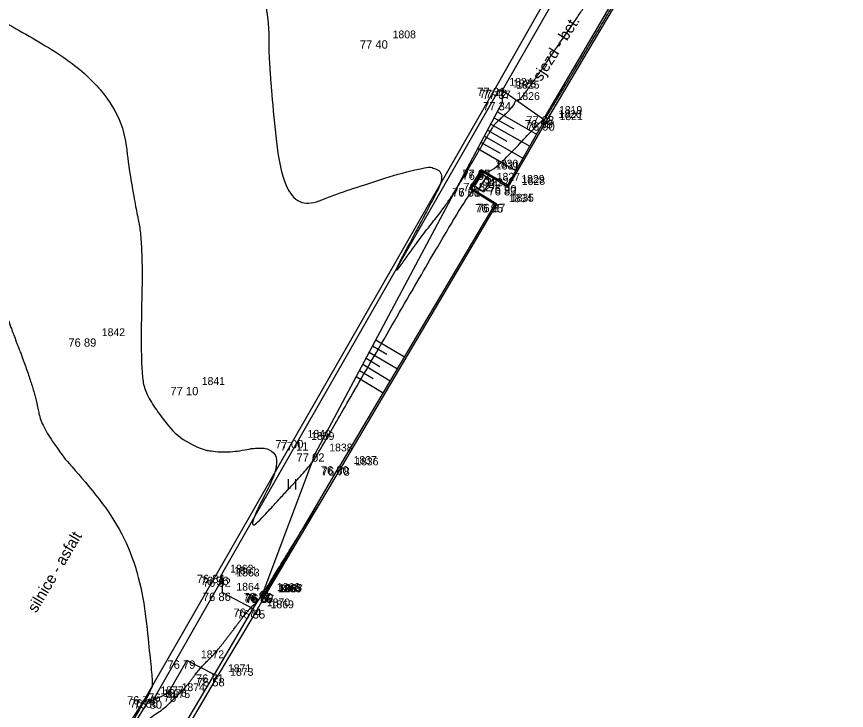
# Model space of a CAD drawing. Extents: x -704017 to -701500, y -1008977 to -1008450.
# Drawn here: x -701574.39 to -701544.66, y -1008544.23 to -1008519.37 of the extents above; entities that cross this region are included whole.
import ezdxf

# ---------------------------------------------------------------- set-up
doc = ezdxf.new("R2010")
doc.units = 0
for name, color, linetype in [('Z_body', 7, 'Continuous'), ('Z_body_cisla', 7, 'Continuous'), ('Z_body_vysky', 7, 'Continuous'), ('Z_chodnik', 7, 'Continuous'), ('Z_komunikace', 7, 'Continuous'), ('Z_obruby', 7, 'Continuous'), ('Z_popis', 7, 'Continuous'), ('Z_rozhrani_ploch', 7, 'Continuous'), ('Z_site_znaky_kanalizace', 7, 'Continuous'), ('Z_site_znaky_vodovod', 7, 'Continuous'), ('Z_teren_hrany_paty', 7, 'Continuous'), ('Z_vrstevnice_hlavni', 7, 'Continuous'), ('Z_vrstevnice_vedlejsi', 7, 'Continuous')]:
    doc.layers.add(name, color=color, linetype=linetype)

# ---------------------------------------------------------------- blocks, each defined once
blk = doc.blocks.new('POINT_DISPLAY')
blk.add_line((0, 0), (0, 0))
blk = doc.blocks.new('Z306')
for p, q in [((-0.13, 0.17), (-0.13, -0.2)), ((0.13, 0.17), (0.13, -0.2))]:
    blk.add_line(p, q)
blk = doc.blocks.new('Z38')
for p, q in [((0.25, 0.2), (-0.25, 0.2)), ((-0.25, 0.2), (-0.25, -0.2)), ((-0.25, 0), (0.25, 0)), ((0.25, -0.2), (0.25, 0.2)), ((-0.25, -0.2), (0.25, -0.2))]:
    blk.add_line(p, q)
blk = doc.blocks.new('Z614')
for p, q in [((-0.13, 0.03), (-0.1, 0.08)), ((-0.13, -0.03), (-0.13, 0.03)), ((-0.1, 0.08), (-0.08, 0.1)), ((-0.08, 0.1), (-0.03, 0.13)), ((-0.03, 0.13), (0.03, 0.13)), ((0.03, 0.13), (0.08, 0.1)), ((0.08, 0.1), (0.1, 0.08)), ((0.1, 0.08), (0.13, 0.03)), ((0.13, 0.03), (0.13, -0.03)), ((-0.1, -0.08), (-0.13, -0.03)), ((-0.08, -0.1), (-0.1, -0.08)), ((-0.03, -0.13), (-0.08, -0.1)), ((0.03, -0.13), (-0.03, -0.13)), ((0.08, -0.1), (0.03, -0.13)), ((0.1, -0.08), (0.08, -0.1)), ((0.13, -0.03), (0.1, -0.08))]:
    blk.add_line(p, q)

msp = doc.modelspace()

# ---------------------------------------------------------------- linework, layer by layer
at = {"layer": 'Z_chodnik'}
for p, q in [((-701552.79, -1008518.67), (-701555.44, -1008523.16)), ((-701555.44, -1008523.16), (-701556.79, -1008525.48)), ((-701557.72, -1008524.92), (-701558.09, -1008525.52)), ((-701556.79, -1008525.48), (-701557.72, -1008524.92)), ((-701558.09, -1008525.52), (-701557.19, -1008526.08)), ((-701557.19, -1008526.08), (-701562.76, -1008535.52)), ((-701562.76, -1008535.52), (-701565.47, -1008540.08)), ((-701565.47, -1008540.08), (-701565.79, -1008540.64)), ((-701565.79, -1008540.64), (-701567.24, -1008543.07)), ((-701567.24, -1008543.07), (-701568.22, -1008544.75))]:
    msp.add_line(p, q, dxfattribs=at)
at = {"layer": 'Z_komunikace'}
for p, q in [((-701554.72, -1008517.51), (-701557.24, -1008521.92)), ((-701557.24, -1008521.92), (-701564.47, -1008534.54)), ((-701564.47, -1008534.54), (-701567.24, -1008539.37)), ((-701569.74, -1008543.72), (-701567.24, -1008539.37)), ((-701569.74, -1008543.72), (-701571.74, -1008546.87))]:
    msp.add_line(p, q, dxfattribs=at)
at = {"layer": 'Z_obruby'}
for p, q in [((-701554.5, -1008517.65), (-701556.99, -1008522.02)), ((-701553.11, -1008518.96), (-701555.46, -1008522.94)), ((-701557.11, -1008521.99), (-701564.34, -1008534.62)), ((-701556.99, -1008522.02), (-701557.11, -1008521.99)), ((-701555.48, -1008523.08), (-701556.81, -1008525.41)), ((-701555.46, -1008522.94), (-701555.48, -1008523.08)), ((-701557.75, -1008524.86), (-701558.16, -1008525.52)), ((-701556.81, -1008525.41), (-701557.75, -1008524.86)), ((-701558.16, -1008525.52), (-701557.26, -1008526.09)), ((-701557.26, -1008526.09), (-701562.82, -1008535.48)), ((-701564.34, -1008534.62), (-701567.1, -1008539.44)), ((-701565.5, -1008540.05), (-701562.82, -1008535.48)), ((-701567.1, -1008539.44), (-701567.02, -1008539.5)), ((-701567.02, -1008539.5), (-701569.51, -1008543.87)), ((-701565.57, -1008540.02), (-701565.93, -1008540.58)), ((-701565.5, -1008540.05), (-701565.57, -1008540.02)), ((-701565.93, -1008540.58), (-701567.32, -1008542.94)), ((-701567.32, -1008542.94), (-701568.33, -1008544.65)), ((-701569.63, -1008543.83), (-701571.63, -1008546.96)), ((-701569.51, -1008543.87), (-701569.63, -1008543.83))]:
    msp.add_line(p, q, dxfattribs=at)
at = {"layer": 'Z_rozhrani_ploch'}
for p, q in [((-701555.48, -1008523.08), (-701556.99, -1008522.02)), ((-701555.46, -1008522.94), (-701555.48, -1008523.08)), ((-701567.02, -1008540.01), (-701567.02, -1008539.5)), ((-701567.02, -1008540.01), (-701565.93, -1008540.58)), ((-701568.29, -1008542.44), (-701568.98, -1008543.62)), ((-701567.32, -1008542.94), (-701568.29, -1008542.44)), ((-701568.98, -1008543.62), (-701569.51, -1008543.87))]:
    msp.add_line(p, q, dxfattribs=at)
at = {"layer": 'Z_teren_hrany_paty'}
for p, q in [((-701556.98, -1008522.43), (-701556.99, -1008522.02)), ((-701556.98, -1008522.43), (-701563.69, -1008535.02)), ((-701557.16, -1008522.78), (-701555.76, -1008523.58)), ((-701557.28, -1008523), (-701556.58, -1008523.39)), ((-701557.4, -1008523.22), (-701556.01, -1008524.01)), ((-701557.63, -1008523.66), (-701556.26, -1008524.44)), ((-701557.52, -1008523.44), (-701556.83, -1008523.83)), ((-701557.75, -1008523.88), (-701557.07, -1008524.27)), ((-701557.87, -1008524.1), (-701556.51, -1008524.88)), ((-701561.52, -1008530.95), (-701560.5, -1008531.56)), ((-701561.76, -1008531.39), (-701560.75, -1008531.99)), ((-701561.64, -1008531.17), (-701561.13, -1008531.47)), ((-701561.87, -1008531.61), (-701561.38, -1008531.91)), ((-701561.99, -1008531.83), (-701561.01, -1008532.42)), ((-701562.23, -1008532.27), (-701561.26, -1008532.85)), ((-701562.11, -1008532.05), (-701561.62, -1008532.34)), ((-701563.69, -1008535.02), (-701565.57, -1008540.02))]:
    msp.add_line(p, q, dxfattribs=at)
at = {"layer": 'Z_vrstevnice_hlavni'}
msp.add_open_spline([(-701579.898, -1008517.403), (-701579.435, -1008517.461), (-701579.227, -1008517.484), (-701578.62, -1008517.429), (-701578.136, -1008517.429), (-701578.069, -1008517.412), (-701577.945, -1008517.378), (-701577.257, -1008518.262), (-701570.798, -1008521.775), (-701570.216, -1008525.84), (-701569.854, -1008527.425), (-701569.965, -1008531.811), (-701569.749, -1008533.131), (-701567.868, -1008535.228), (-701564.47, -1008534.54), (-701566.364, -1008538.155), (-701564.827, -1008536.493), (-701563.84, -1008535.42), (-701563.611, -1008535.062), (-701558.382, -1008525.994), (-701558.01, -1008525.615), (-701558.155, -1008525.52), (-701557.85, -1008525.054), (-701557.738, -1008524.883), (-701557.437, -1008525.043), (-701555.858, -1008523.377), (-701555.523, -1008523.061), (-701555.52, -1008523.052), (-701555.478, -1008523.064), (-701555.451, -1008523.038), (-701554.427, -1008521.334), (-701552.912, -1008518.78), (-701552.83, -1008518.643), (-701552.822, -1008518.618), (-701552.869, -1008518.575), (-701552.419, -1008517.944), (-701552.058, -1008517.342), (-701550.92, -1008515.45), (-701550.945, -1008516.008)], degree=2, dxfattribs=at)
at = {"layer": 'Z_vrstevnice_vedlejsi'}
for points in [[(-701575.752, -1008514.26), (-701574.817, -1008512.777), (-701573.926, -1008511.316), (-701570.695, -1008512.711), (-701569.42, -1008512.917), (-701566.67, -1008515.095), (-701566.175, -1008515.153), (-701565.67, -1008518.087), (-701565.342, -1008519.528), (-701565.377, -1008520.923), (-701564.84, -1008526.43), (-701562.564, -1008525.59), (-701558.639, -1008524.363), (-701560.089, -1008527.07), (-701561.075, -1008528.916), (-701559.86, -1008527.2), (-701558.867, -1008525.971), (-701557.302, -1008523.273), (-701557.219, -1008523.184), (-701556.594, -1008522.597), (-701556.513, -1008522.355), (-701556.357, -1008522.401), (-701554.888, -1008520.254), (-701553.753, -1008518.595), (-701553.721, -1008518.39), (-701553.438, -1008518.164), (-701553.603, -1008518.013), (-701550.512, -1008513.673), (-701549.42, -1008512.077), (-701548.525, -1008510.814), (-701546.565, -1008507.745), (-701545.255, -1008505.496), (-701544.661, -1008504.504)], [(-701581.484, -1008520.098), (-701581.044, -1008520.351), (-701576.589, -1008526.756), (-701576.279, -1008527.273), (-701576.148, -1008527.441), (-701575.257, -1008527.926), (-701575.052, -1008529.352), (-701573.738, -1008532.728), (-701573.472, -1008534.358), (-701570.098, -1008538.119), (-701569.49, -1008543.285), (-701569.589, -1008543.486), (-701569.702, -1008543.745), (-701569.731, -1008543.729), (-701570.49, -1008545.069), (-701570.924, -1008545.855), (-701569.908, -1008544.918), (-701569.741, -1008544.578), (-701569.089, -1008544.149), (-701568.817, -1008543.878), (-701568.269, -1008543.329), (-701567.805, -1008542.69), (-701567.24, -1008542.159), (-701566.021, -1008540.533), (-701565.81, -1008540.393), (-701565.563, -1008540.03), (-701565.552, -1008540.028), (-701564.038, -1008537.557), (-701563.673, -1008537.03), (-701563.499, -1008536.764)], [(-701583.758, -1008524.378), (-701583.725, -1008524.396), (-701583.247, -1008525.084), (-701581.8, -1008527.754), (-701577.643, -1008535.405), (-701577.276, -1008535.989), (-701577.056, -1008537.148), (-701576.362, -1008543.879), (-701576.184, -1008545.1), (-701576.039, -1008545.424), (-701575.362, -1008546.368), (-701572.955, -1008548.603), (-701573.208, -1008549.082), (-701573.733, -1008549.961), (-701572.633, -1008549.614), (-701571.446, -1008548.497), (-701569.669, -1008545.652), (-701568.82, -1008545.14), (-701568.628, -1008545.02), (-701569.284, -1008546.389), (-701568.639, -1008545.441), (-701568.592, -1008545.371), (-701568.307, -1008545.091)], [(-701586.638, -1008530.149), (-701583.606, -1008535.727), (-701581.404, -1008539.231), (-701581.171, -1008540.459), (-701580.149, -1008543.901), (-701579.652, -1008547.301), (-701578.785, -1008549.245), (-701576.755, -1008552.075), (-701575.994, -1008552.799), (-701577.127, -1008554.481), (-701577.189, -1008554.565), (-701577.075, -1008554.54), (-701577.032, -1008554.582), (-701576.659, -1008554.828), (-701574.932, -1008553.415), (-701573.952, -1008553.106), (-701573.41, -1008552.597), (-701571.145, -1008548.968), (-701572.423, -1008551.634), (-701572.129, -1008551.201), (-701571.692, -1008550.549), (-701571.051, -1008549.918)]]:
    msp.add_open_spline(points, degree=2, dxfattribs=at)

# ---------------------------------------------------------------- block references
at = {"layer": 'Z_body'}
for p in [(-701561.42, -1008520.22), (-701557.24, -1008521.92), (-701557.11, -1008521.99), (-701556.99, -1008522.02), (-701556.98, -1008522.43), (-701555.48, -1008523.08), (-701555.46, -1008522.94), (-701555.44, -1008523.16), (-701557.75, -1008524.86), (-701557.72, -1008524.92), (-701557.69, -1008525.33), (-701556.81, -1008525.41), (-701556.79, -1008525.48), (-701558.16, -1008525.52), (-701558.09, -1008525.52), (-701557.26, -1008526.09), (-701557.19, -1008526.08), (-701571.84, -1008530.9), (-701568.26, -1008532.64), (-701564.47, -1008534.54), (-701564.34, -1008534.62), (-701563.69, -1008535.02), (-701562.82, -1008535.48), (-701562.76, -1008535.52), (-701567.24, -1008539.37), (-701567.1, -1008539.44), (-701567.02, -1008539.5), (-701567.02, -1008540.01), (-701565.57, -1008540.02), (-701565.5, -1008540.05), (-701565.53, -1008540.08), (-701565.47, -1008540.08), (-701565.93, -1008540.58), (-701565.79, -1008540.64), (-701568.29, -1008542.44), (-701567.32, -1008542.94), (-701567.24, -1008543.07), (-701569.74, -1008543.72), (-701569.63, -1008543.83), (-701569.51, -1008543.87), (-701568.98, -1008543.62)]:
    msp.add_blockref('POINT_DISPLAY', p, dxfattribs=at)
at = {"layer": 'Z_popis'}
msp.add_blockref('Z306', (-701564.53, -1008536.11), dxfattribs=at)
at = {"layer": 'Z_site_znaky_kanalizace', "rotation": 58.5}
msp.add_blockref('Z38', (-701557.69, -1008525.33), dxfattribs=at)
at = {"layer": 'Z_site_znaky_vodovod', "rotation": 10.799999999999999}
msp.add_blockref('Z614', (-701565.53, -1008540.08), dxfattribs=at)

# ---------------------------------------------------------------- texts
at = {"layer": 'Z_body_cisla'}
for s, p in [('1808', (-701560.92, -1008520.15)), ('1824', (-701556.74, -1008521.85)), ('1823', (-701556.61, -1008521.91)), ('1825', (-701556.49, -1008521.95)), ('1826', (-701556.48, -1008522.36)), ('1820', (-701554.98, -1008523)), ('1819', (-701554.96, -1008522.86)), ('1821', (-701554.94, -1008523.08)), ('1830', (-701557.25, -1008524.78)), ('1831', (-701557.22, -1008524.85)), ('940', (-701557.66, -1008525.45)), ('1832', (-701557.59, -1008525.45)), ('1827', (-701557.19, -1008525.25)), ('1829', (-701556.31, -1008525.33)), ('1828', (-701556.29, -1008525.4)), ('1834', (-701556.76, -1008526.02)), ('1835', (-701556.69, -1008526)), ('1842', (-701571.34, -1008530.82)), ('1841', (-701567.76, -1008532.57)), ('1840', (-701563.97, -1008534.46)), ('1839', (-701563.84, -1008534.54)), ('1838', (-701563.19, -1008534.95)), ('1837', (-701562.32, -1008535.4)), ('1836', (-701562.26, -1008535.45)), ('1862', (-701566.74, -1008539.29)), ('1861', (-701566.6, -1008539.36)), ('1863', (-701566.52, -1008539.43)), ('1864', (-701566.52, -1008539.94)), ('1866', (-701565.07, -1008539.95)), ('1868', (-701565.03, -1008540)), ('1865', (-701565, -1008539.98)), ('1867', (-701564.97, -1008540)), ('1870', (-701565.43, -1008540.5)), ('1869', (-701565.29, -1008540.57)), ('1872', (-701567.79, -1008542.36)), ('1871', (-701566.82, -1008542.86)), ('1873', (-701566.74, -1008542.99)), ('1874', (-701568.48, -1008543.54)), ('1877', (-701569.24, -1008543.65)), ('1876', (-701569.13, -1008543.75)), ('1875', (-701569.01, -1008543.79))]:
    msp.add_text(s, height=0.28, dxfattribs=at).set_placement(p)
at = {"layer": 'Z_body_vysky'}
for s, p in [('77 40', (-701562.095, -1008520.52)), ('77 31', (-701557.89, -1008522.22)), ('77 42', (-701557.81, -1008522.29)), ('77 37', (-701557.69, -1008522.32)), ('77 34', (-701557.68, -1008522.73)), ('76 99', (-701556.18, -1008523.38)), ('77 08', (-701556.135, -1008523.24)), ('76 90', (-701556.115, -1008523.46)), ('77 05', (-701558.425, -1008525.16)), ('76 92', (-701558.42, -1008525.22)), ('76 82', (-701558.39, -1008525.63)), ('76 83', (-701557.49, -1008525.78)), ('76 90', (-701557.485, -1008525.71)), ('76 88', (-701558.79, -1008525.82)), ('77 01', (-701558.785, -1008525.82)), ('76 87', (-701557.89, -1008526.38)), ('76 95', (-701557.96, -1008526.39)), ('76 89', (-701572.54, -1008531.2)), ('77 10', (-701568.885, -1008532.94)), ('77 00', (-701565.12, -1008534.84)), ('77 11', (-701564.94, -1008534.92)), ('77 02', (-701564.365, -1008535.32)), ('76 80', (-701563.495, -1008535.78)), ('76 78', (-701563.46, -1008535.82)), ('76 84', (-701567.94, -1008539.67)), ('76 96', (-701567.8, -1008539.74)), ('76 92', (-701567.72, -1008539.8)), ('76 86', (-701567.72, -1008540.31)), ('76 77', (-701566.27, -1008540.32)), ('76 69', (-701566.2, -1008540.35)), ('76 65', (-701566.23, -1008540.38)), ('76 67', (-701566.17, -1008540.38)), ('76 74', (-701566.63, -1008540.88)), ('76 55', (-701566.49, -1008540.94)), ('76 79', (-701568.99, -1008542.74)), ('76 71', (-701567.97, -1008543.24)), ('76 58', (-701567.94, -1008543.37)), ('76 78', (-701569.68, -1008543.92)), ('76 74', (-701570.44, -1008544.02)), ('76 86', (-701570.33, -1008544.13)), ('76 80', (-701570.185, -1008544.17))]:
    msp.add_text(s, height=0.3, dxfattribs=at).set_placement(p)
at = {"layer": 'Z_popis'}
for s, rotation, p in [('sjezd - bet.', 57.6, (-701555.6, -1008521.72)), ('silnice - asfalt', 59.4, (-701573.69, -1008540.76))]:
    msp.add_text(s, height=0.4, rotation=rotation, dxfattribs=at).set_placement(p)

doc.saveas('drawing.dxf')
